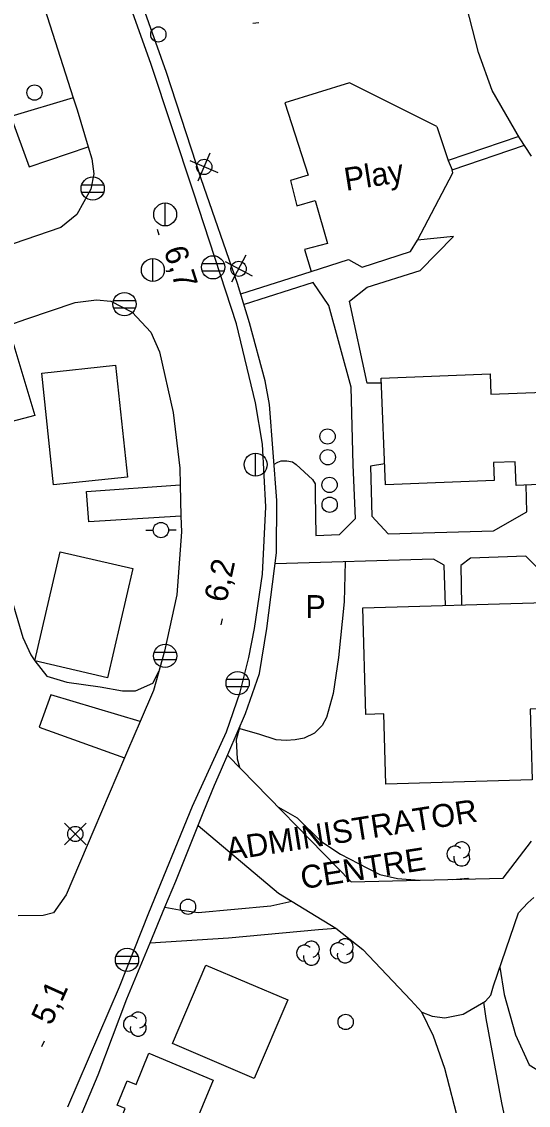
# Model space of a CAD drawing. Extents: x 646142 to 649934, y 5874075 to 5876351.
# Drawn here: x 647045 to 647111.3, y 5874400.3 to 5874542.2 of the extents above; entities that cross this region are included whole.
import ezdxf

# ---------------------------------------------------------------- set-up
doc = ezdxf.new("R2010")
doc.units = 0
for name, color, linetype in [('Niveau 19', 7, 'Continuous'), ('Niveau 2', 7, 'Continuous'), ('Niveau 21', 7, 'Continuous'), ('Niveau 22', 7, 'Continuous'), ('Niveau 3', 7, 'Continuous'), ('Niveau 31', 7, 'Continuous'), ('Niveau 36', 7, 'Continuous'), ('Niveau 44', 7, 'Continuous'), ('Niveau 52', 7, 'Continuous'), ('Niveau 56', 7, 'Continuous')]:
    doc.layers.add(name, color=color, linetype=linetype)

msp = doc.modelspace()

# ---------------------------------------------------------------- linework, layer by layer
at = {"layer": 'Niveau 19'}
for points in [[(647111.68, 5874524.61), (647110.14, 5874526.97), (647106.53, 5874533.19), (647104.78, 5874538.16), (647102.81, 5874545.84)], [(647051.75, 5874532.21), (647043.57, 5874529.78), (647045.97, 5874523.19), (647053.7, 5874525.8)], [(647043.17, 5874502.43), (647046.71, 5874490.65), (647042.95, 5874489.64), (647039.52, 5874501.19)], [(647065.84, 5874477.47), (647053.8, 5874476.71), (647053.47, 5874480.67), (647065.74, 5874481.55)], [(647060.5, 5874450.56), (647048.8, 5874454.05), (647047.28, 5874449.82), (647058.44, 5874445.8)], [(647071.92, 5874446.18), (647088.12, 5874429.6), (647108, 5874430.06), (647111.68, 5874434.89)], [(647068.1, 5874436.96), (647078.61, 5874428.12), (647086.09, 5874423.52), (647089.65, 5874420.71), (647095.89, 5874414.1), (647097.35, 5874412.51), (647098.68, 5874411.99), (647100.37, 5874411.79), (647102.76, 5874412.27), (647105.69, 5874413.98), (647106.38, 5874414.74), (647106.72, 5874415.96), (647110, 5874425.54), (647111.21, 5874426.85), (647112.01, 5874427.53)], [(647063.75, 5874426.25), (647065.64, 5874425.94), (647068.11, 5874425.56), (647077.59, 5874426.46), (647080.33, 5874427.06)], [(647061.82, 5874421.62), (647072.06, 5874422.27), (647083.85, 5874423.36), (647086.1, 5874423.51)], [(647032.53, 5874330.41), (647041.56, 5874326.22), (647056.32, 5874320.56), (647069.37, 5874315.43), (647075.81, 5874313.81), (647078.75, 5874313.98), (647082.36, 5874314.69), (647087.05, 5874316.34), (647089.38, 5874317.99), (647093.28, 5874324.07), (647099.58, 5874339.63), (647104.2, 5874350.52), (647109.53, 5874361.36), (647111.22, 5874369.47), (647111.82, 5874376.64), (647111.47, 5874380.25), (647110.9, 5874386.03), (647107.81, 5874400.67), (647105.74, 5874411.68), (647105.46, 5874413.84)], [(647102.25, 5874397.92), (647100.37, 5874405.15), (647098.86, 5874409.37), (647097.35, 5874412.51)]]:
    msp.add_lwpolyline(points, dxfattribs=at)
at = {"layer": 'Niveau 2'}
for points in [[(647036.2, 5874500.06), (647036.44, 5874497.88), (647037.1, 5874494.71), (647039, 5874490.06), (647041.64, 5874486.99), (647043.25, 5874483.79), (647043.77, 5874480.25), (647043.47, 5874475.42), (647043.29, 5874472.65), (647043.51, 5874467.22), (647045.14, 5874461.56), (647046.2, 5874459.3), (647046.72, 5874458.5), (647048.29, 5874456.51), (647050.91, 5874455.73), (647055.27, 5874455.1), (647058.17, 5874454.58), (647059.91, 5874454.6), (647062.16, 5874455.61), (647062.98, 5874457.21)], [(647073.53, 5874449.92), (647073.07, 5874448.19), (647073.17, 5874445.68), (647073.48, 5874444.58)], [(647078.59, 5874439.35), (647081.02, 5874437.95), (647084.12, 5874434.93), (647086.71, 5874433.21), (647090.23, 5874431.39), (647091.87, 5874430.53), (647094.18, 5874430.02), (647097.06, 5874429.81)], [(647101.34, 5874429.91), (647103.37, 5874430.08), (647103.51, 5874429.96)], [(647107.57, 5874418.42), (647108.12, 5874414.83), (647109.6, 5874409.57), (647111.38, 5874405.61), (647113.16, 5874404.53), (647114.73, 5874404.15)]]:
    msp.add_lwpolyline(points, dxfattribs=at)
at = {"layer": 'Niveau 21'}
for points in [[(647051.03, 5874400.13), (647057.78, 5874415.82), (647061.64, 5874425.52), (647067.36, 5874439.48), (647071.8, 5874449.22), (647073.58, 5874454.41), (647074.72, 5874458.95), (647075.46, 5874462.76), (647076.5, 5874469.88), (647076.93, 5874478.7), (647076.49, 5874486.87), (647075.58, 5874492.29), (647073.1, 5874502.63), (647067.49, 5874519.86), (647061.91, 5874536.73), (647058.44, 5874546.4)], [(647047.69, 5874544.91), (647051.75, 5874532.21), (647052.24, 5874530.65), (647053.7, 5874525.8), (647054.17, 5874524.25), (647054.45, 5874522.28), (647054.03, 5874520.25), (647052.21, 5874516.94), (647050.14, 5874515.25), (647043.91, 5874513.1), (647031.78, 5874509.18), (647019.3, 5874505.11), (647012.71, 5874502.92), (647008.03, 5874501.36), (647004.32, 5874500.12), (647000.37, 5874498.82), (646992.96, 5874496.37), (646984.45, 5874493.57), (646974.99, 5874490.59)], [(647043.17, 5874502.43), (647045.67, 5874503.28), (647052.01, 5874505.45), (647054.78, 5874505.79), (647056.66, 5874505.59), (647059.45, 5874504.18), (647061.88, 5874501.57), (647063.02, 5874498.97), (647064.84, 5874491.04), (647065.68, 5874483.73), (647065.74, 5874481.55), (647065.84, 5874477.47), (647065.9, 5874475.43), (647065.3, 5874467.18), (647063.7, 5874459.78), (647062.26, 5874454.62), (647060.5, 5874450.56), (647058.83, 5874446.72), (647058.44, 5874445.8), (647054.44, 5874436.39), (647050.83, 5874427.89), (647049.17, 5874425.52), (647047.8, 5874425.17), (647044.53, 5874425.14)]]:
    msp.add_lwpolyline(points, dxfattribs=at)
at = {"layer": 'Niveau 22'}
for points in [[(647049.9, 5874392.2), (647054.99, 5874404.31), (647058.76, 5874414.26), (647061.82, 5874421.62), (647063.75, 5874426.25), (647065.17, 5874429.68), (647068.85, 5874438.82), (647070.21, 5874442.23), (647070.99, 5874444.04), (647074.26, 5874451.61), (647076.11, 5874456.88), (647077.07, 5874462.76), (647078.35, 5874472.68), (647078.39, 5874479.53), (647077.4, 5874492.06), (647076.86, 5874495.19), (647074.82, 5874502.78), (647073.25, 5874507.93), (647068.5, 5874521.61), (647063.95, 5874535.54), (647060.22, 5874546.01)], [(647110.03, 5874527.16), (647100.79, 5874524.03), (647101.3, 5874522.82), (647110.77, 5874526.01)], [(647073.67, 5874506.57), (647082.86, 5874509.5), (647087.76, 5874511.05), (647089.54, 5874510.04), (647095.88, 5874512.1), (647096.77, 5874513.59)], [(647092.07, 5874494.89), (647090.18, 5874494.85), (647087.89, 5874505.62), (647090.21, 5874507.45), (647097.13, 5874509.63), (647101.49, 5874514.09), (647096.77, 5874513.59)], [(647078.01, 5874484.28), (647078.52, 5874484.54), (647078.94, 5874484.69), (647079.67, 5874484.72), (647080.42, 5874484.57), (647080.9, 5874484.23), (647083.03, 5874482.28), (647083.39, 5874481.69), (647083.4, 5874480.37), (647083.46, 5874474.91), (647086.56, 5874475.07), (647088.66, 5874477.17), (647088.37, 5874484.17), (647088.11, 5874494.35), (647085.2, 5874505.04), (647083.14, 5874508.07), (647074.1, 5874505.15)], [(647092.49, 5874484.29), (647090.62, 5874484.02), (647090.8, 5874477.45), (647092.93, 5874475.16), (647106.74, 5874475.56), (647111.08, 5874478.02), (647110.98, 5874481.53)], [(647113.87, 5874452.55), (647114.42, 5874452.47), (647114.82, 5874453.2), (647114.25, 5874468.91), (647110.93, 5874472.23), (647103.7, 5874471.97), (647102.45, 5874470.99), (647102.54, 5874465.84)], [(647100.43, 5874465.78), (647100.26, 5874471.03), (647098.89, 5874471.85), (647078.16, 5874471.21)]]:
    msp.add_lwpolyline(points, dxfattribs=at)
at = {"layer": 'Niveau 3'}
for p, q in [((647075.22, 5874541.99), (647076.01, 5874542.11)), ((647062.71, 5874515.05), (647062.95, 5874514.29)), ((647071.11, 5874463.23), (647071.28, 5874464.01)), ((647047.65, 5874408.05), (647047.97, 5874408.78))]:
    msp.add_line(p, q, dxfattribs=at)
at = {"layer": 'Niveau 31'}
for points in [[(647049.18, 5874481.54), (647047.62, 5874496.19), (647057.29, 5874497.21), (647058.84, 5874482.56), (647049.18, 5874481.54)], [(647114.76, 5874481.68), (647109.68, 5874481.48), (647109.56, 5874484.59), (647106.72, 5874484.48), (647106.81, 5874482.14), (647092.6, 5874481.57), (647092.04, 5874495.52), (647106.28, 5874496.09), (647106.39, 5874493.42), (647116.72, 5874493.83)], [(647046.72, 5874458.5), (647050.02, 5874472.79), (647059.54, 5874470.59), (647056.25, 5874456.3), (647046.72, 5874458.5)], [(647089.62, 5874465.47), (647113.48, 5874466.15), (647113.88, 5874452.28), (647111.51, 5874452.21), (647111.77, 5874442.92), (647092.63, 5874442.37), (647092.37, 5874451.58), (647090.02, 5874451.51), (647089.62, 5874465.47)], [(647064.73, 5874408.41), (647069.1, 5874418.69), (647079.8, 5874414.14), (647075.43, 5874403.86), (647064.73, 5874408.41)], [(647070.05, 5874403.64), (647064.49, 5874390.18), (647056.13, 5874393.76), (647058.55, 5874399.9), (647057.48, 5874400.34), (647058.81, 5874403.54), (647059.96, 5874403.07), (647061.62, 5874407.16), (647070.05, 5874403.64), (647070.05, 5874403.64)]]:
    msp.add_lwpolyline(points, dxfattribs=at)
at = {"layer": 'Niveau 36'}
for p, q in [((647068.09, 5874521.35), (647069.68, 5874525.01)), ((647070.71, 5874522.39), (647067.05, 5874523.97)), ((647055.73, 5874520.8), (647052.85, 5874520.8)), ((647052.85, 5874519.88), (647055.73, 5874519.88)), ((647063.78, 5874515.45), (647063.78, 5874518.45)), ((647062.17, 5874508.17), (647062.17, 5874511.17)), ((647071.48, 5874510.49), (647068.6, 5874510.49)), ((647071.62, 5874510.78), (647075.15, 5874508.91)), ((647074.31, 5874511.61), (647072.45, 5874508.08)), ((647068.6, 5874509.57), (647071.48, 5874509.57)), ((647059.89, 5874505.67), (647057.01, 5874505.67)), ((647057.01, 5874504.75), (647059.89, 5874504.75)), ((647075.6, 5874482.7), (647075.6, 5874485.7)), ((647061.23, 5874475.64), (647062.23, 5874475.64)), ((647065.23, 5874475.64), (647064.23, 5874475.64)), ((647065.2, 5874459.61), (647062.32, 5874459.61)), ((647062.32, 5874458.69), (647065.2, 5874458.69)), ((647074.69, 5874456.06), (647071.81, 5874456.06)), ((647071.81, 5874455.14), (647074.69, 5874455.14)), ((647053.43, 5874434.44), (647050.61, 5874437.26)), ((647050.61, 5874434.44), (647053.43, 5874437.26)), ((647060.22, 5874419.82), (647057.34, 5874419.82)), ((647057.34, 5874418.9), (647060.22, 5874418.9))]:
    msp.add_line(p, q, dxfattribs=at)
for centre, radius in [((647062.88, 5874540.53), 1), ((647046.68, 5874532.91), 1), ((647068.88, 5874523.19), 1), ((647054.29, 5874520.35), 1.52), ((647063.77, 5874516.96), 1.5), ((647062.16, 5874509.68), 1.5), ((647070.04, 5874510.04), 1.52), ((647073.38, 5874509.84), 1), ((647058.45, 5874505.22), 1.52), ((647085.01, 5874487.89), 1), ((647085.04, 5874485.18), 1), ((647075.6, 5874484.21), 1.5), ((647085.27, 5874481.55), 1), ((647085.29, 5874478.96), 1), ((647063.22, 5874475.64), 1), ((647063.76, 5874459.16), 1.52), ((647073.25, 5874455.61), 1.52), ((647052.02, 5874435.85), 1), ((647066.76, 5874426.33), 1), ((647058.78, 5874419.37), 1.52), ((647087.38, 5874411.24), 1)]:
    msp.add_circle(centre, radius, dxfattribs=at)
at = {"layer": 'Niveau 44'}
for centre, start, end in [((647101.67, 5874433.23), 44.1154, 269.804), ((647102.57, 5874433.76), 282.2692, 149.7263), ((647102.57, 5874432.71), 166.9369, 29.6212), ((647082, 5874420.24), 44.1154, 269.804), ((647082.9, 5874420.77), 282.2692, 149.7263), ((647086.42, 5874420.55), 44.1154, 269.804), ((647087.32, 5874421.08), 282.2692, 149.7263), ((647082.9, 5874419.72), 166.9369, 29.6212), ((647087.32, 5874420.03), 166.9369, 29.6212), ((647060.25, 5874411.48), 282.2692, 149.7263), ((647059.35, 5874410.95), 44.1154, 269.804), ((647060.25, 5874410.43), 166.9369, 29.6212)]:
    msp.add_arc(centre, 1.05, start, end, dxfattribs=at)
at = {"layer": 'Niveau 52'}
msp.add_lwpolyline([(647087.31, 5874471.49), (647087.19, 5874466.25), (647086.43, 5874458.94), (647085.76, 5874454.26), (647084.86, 5874451.08), (647084.3, 5874450.04), (647083.3, 5874449.04), (647081.96, 5874448.4), (647080.76, 5874448.16), (647079.6, 5874448.07), (647078.27, 5874448.16), (647076.03, 5874448.93), (647073.41, 5874449.64)], dxfattribs=at)
at = {"layer": 'Niveau 56'}
for points in [[(647099.3, 5874528.46), (647087.89, 5874534.18), (647079.43, 5874531.58), (647082.47, 5874522.1), (647080.18, 5874521.4), (647080.98, 5874518.07), (647083.39, 5874518.77), (647085, 5874513.16), (647082.01, 5874512.39), (647082.86, 5874509.5)], [(647099.3, 5874528.46), (647100.79, 5874524.03)], [(647096.77, 5874513.59), (647101.42, 5874522.43), (647101.3, 5874522.82)]]:
    msp.add_lwpolyline(points, dxfattribs=at)

# ---------------------------------------------------------------- texts
at = {"layer": 'Niveau 3'}
for s, rotation, p in [('6,7  ', 287.7609, (647063.55, 5874512.3)), ('6,2  ', 77.7168, (647071.76, 5874466.03)), ('5,1  ', 65.7869, (647048.86, 5874410.66))]:
    msp.add_text(s, height=3, rotation=rotation, dxfattribs=at).set_placement(p)
at = {"layer": 'Niveau 31'}
for s, p in [('ADMINISTRATOR', (647071.97, 5874432.33)), ('CENTRE', (647081.73, 5874428.61))]:
    msp.add_text(s, height=3, rotation=8.941, dxfattribs=at).set_placement(p)
at = {"layer": 'Niveau 52'}
msp.add_text('P', height=3, dxfattribs=at).set_placement((647082.11, 5874464.12))
at = {"layer": 'Niveau 56'}
msp.add_text('Play', height=3, rotation=8.9405, dxfattribs=at).set_placement((647087.43, 5874520.04))

doc.saveas('drawing.dxf')
